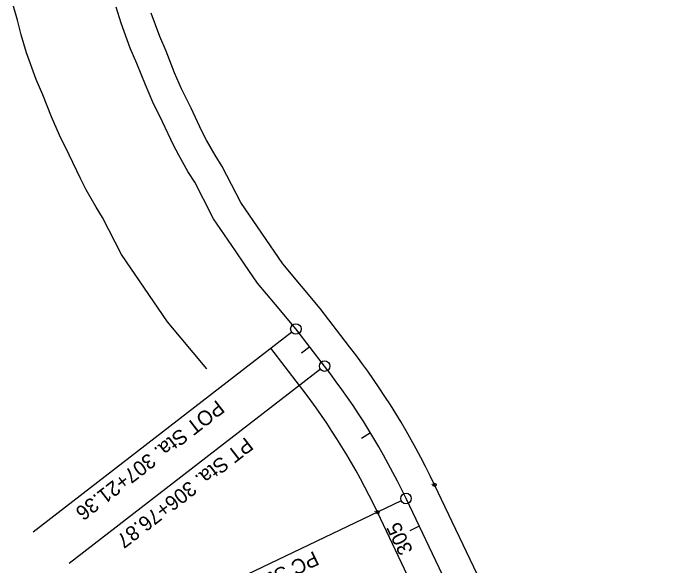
# Model space of a CAD drawing. Extents: x 2080098 to 2083965, y 589975 to 598027.
# Drawn here: x 2082356 to 2082985, y 593478 to 594001 of the extents above; entities that cross this region are included whole.
import ezdxf

# ---------------------------------------------------------------- set-up
doc = ezdxf.new("R2010")
doc.units = 0
for name, color, linetype in [('GE_X_CL_100', 7, 'Continuous'), ('RW_X_CL_20', 7, 'Continuous'), ('RW_X_Esmt_SH', 7, 'Continuous'), ('SV_P_Mon_Cells_Set', 7, 'Continuous'), ('SV_X_Text_Name', 7, 'Continuous')]:
    doc.layers.add(name, color=color, linetype=linetype)

msp = doc.modelspace()

# ---------------------------------------------------------------- linework, layer by layer
at = {"layer": 'GE_X_CL_100'}
for p, q in [((2082651.25, 593666.86), (2082624.04, 593702.06)), ((2082620.09, 593699), (2082374.9, 593509.53)), ((2082637.1, 593685.16), (2082629.19, 593679.05)), ((2082647.29, 593663.8), (2082409.08, 593479.71)), ((2082694.79, 593603.56), (2082686.26, 593598.36)), ((2082723.98, 593539.19), (2082453.78, 593410.2)), ((2082958.18, 593060.22), (2082728.49, 593541.35)), ((2082741.08, 593514.98), (2082732.05, 593510.67))]:
    msp.add_line(p, q, dxfattribs=at)
for centre in [(2082624.04, 593702.06), (2082651.25, 593666.86), (2082728.49, 593541.35)]:
    msp.add_circle(centre, 5, dxfattribs=at)
msp.add_arc((2082101.49, 593242.01), 694.78, 25.52003, 37.69636, dxfattribs=at)
at = {"layer": 'RW_X_CL_20'}
msp.add_lwpolyline([(2082624.04, 593702.06), (2082604.56, 593725.35), (2082587.64, 593745.57), (2082575.33, 593763.52), (2082566.64, 593776.21), (2082545.86, 593806.51), (2082536.26, 593825.24), (2082528.13, 593841.09), (2082521.62, 593851.43), (2082512.88, 593866.69), (2082507.87, 593876.37), (2082497.53, 593898.5), (2082488.42, 593917.06), (2082481.27, 593933.35), (2082473.14, 593953.86), (2082466.96, 593968.19), (2082458.24, 593991.9), (2082453.68, 594007.21)], dxfattribs=at)
at = {"layer": 'RW_X_Esmt_SH'}
for p, q in [((2082674.99, 593685.2), (2082647.05, 593721.31)), ((2082627.51, 593648.51), (2082600.31, 593683.72)), ((2082985.26, 593073.14), (2082755.56, 593554.27)), ((2082931.11, 593047.29), (2082701.42, 593528.42))]:
    msp.add_line(p, q, dxfattribs=at)
for points in [[(2082539.64, 593664.31), (2082502.32, 593708.92), (2082458.65, 593772.62), (2082440.64, 593807.73), (2082434.5, 593817.49), (2082425.15, 593833.83), (2082419.56, 593844.61), (2082409.08, 593867.04), (2082399.82, 593885.92), (2082392.19, 593903.28), (2082384.02, 593923.89), (2082377.69, 593938.57), (2082368.36, 593963.94), (2082363.3, 593980.96), (2082360.01, 593994.8), (2082355.93, 594009.07)], [(2082647.05, 593721.31), (2082611.57, 593763.71), (2082571.68, 593821.9), (2082554.22, 593855.95), (2082547.35, 593866.88), (2082539.23, 593881.06), (2082534.78, 593889.63), (2082524.59, 593911.46), (2082515.63, 593929.71), (2082508.95, 593944.91), (2082500.86, 593965.33), (2082494.83, 593979.32), (2082486.72, 594001.37)]]:
    msp.add_lwpolyline(points, dxfattribs=at)
for radius in [724.78, 664.78]:
    msp.add_arc((2082101.49, 593242.01), radius, 25.52003, 37.69636, dxfattribs=at)
at = {"layer": 'SV_P_Mon_Cells_Set'}
for centre in [(2082755.56, 593554.27), (2082701.42, 593528.42)]:
    msp.add_circle(centre, 1.5, dxfattribs=at)

# ---------------------------------------------------------------- texts
at = {"layer": 'GE_X_CL_100'}
for s, rotation, p in [('POT Sta. 307+21.36', 217.69636, (2082549.2, 593635.38)), ('PT Sta. 306+76.87', 217.69636, (2082576.4, 593600.17)), ('305', 115.52003, (2082735.4, 593492.06)), ('PC Sta. 305+29.22', 205.52003, (2082641.26, 593491.95))]:
    msp.add_text(s, height=14, rotation=rotation, dxfattribs=at).set_placement(p)
at = {"layer": 'SV_X_Text_Name'}
for s, p in [('RP13', (2082752.13, 593554.27)), ('RP12', (2082698, 593528.42))]:
    msp.add_text(s, height=1.2, dxfattribs=at).set_placement(p)

doc.saveas('drawing.dxf')
